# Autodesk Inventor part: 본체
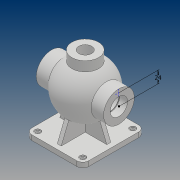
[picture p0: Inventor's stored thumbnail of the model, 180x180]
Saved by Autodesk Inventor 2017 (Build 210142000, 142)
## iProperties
Part Number: 본체
Material: 일반
Document SubType Name: Modeling
Designer: 13
Density: 1 g/cm^3
Appearance: 기본값
Author: 13
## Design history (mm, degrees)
sketch "스케치2"
  geometry: L1 (68, 0)-(-68, 0); L2 (68, 17.5)-(39.278, 17.5); L3 (-68, 17.5)-(-68, 31); L4 (-68, 31)-(-42.988, 31); L5 (42.988, 31)-(68, 31); L6 (68, 31)-(68, 17.5); L7 (-39.278, 17.5)-(-50.25, 17.5); L8 (-50.25, 17.5)-(-50.25, 18.5); L9 (-50.25, 18.5)-(-52, 18.5); L10 (-52, 18.5)-(-52, 17.5); L11 (-52, 17.5)-(-68, 17.5); A1 r 43 centre (0, 0) between (39.278, 17.5) and (-39.278, 17.5); A2 r 53 centre (0, 0) between (42.988, 31) and (-42.988, 31); 2 further points
  constraints: 22 end point, 6 horizontal, 5 point on line, 4 point on circle, 4 vertical, 3 coincident, 2 centre point, 1 midpoint
  dimensions: "d0" = 136 distance of L1.start L1.end; "d1" = 35 diameter of L2 L1; "d2" = 62 diameter of L5 L1; "d4" = 43 radius of A1; "d6" = 53 radius of A2; "d33" = 1.75 distance of L8.end L9.end; "d34" = 37 diameter of L9 L1; "d35" = 35 diameter of L7 L1; "d36" = 16 distance between parallel lines of L3 L10
revolve "회전1" sketch "스케치2" stored, may be unused: angle "d7" = 90 deg
node "작업 평면1"
sketch "스케치3"
  geometry: L1 (-57.5, 62.5)-(57.5, 62.5); L2 (57.5, 62.5)-(57.5, -62.5); L3 (57.5, -62.5)-(-57.5, -62.5); L4 (-57.5, -62.5)-(-57.5, 62.5); L5 (-57.5, 62.5)-(57.5, -62.5); L6 (57.5, 62.5)-(-57.5, -62.5); 1 further point
  constraints: 12 end point, 2 midpoint, 2 parallel, 1 horizontal, 1 perpendicular
  dimensions: "d9" = 115 distance of L2.end L3.end; "d10" = 125 distance of L1.end L2.end
extrude "돌출1" join sketch "스케치3" distance "d11" = 10; taper "d12" = 0 deg
sketch "스케치5"
  geometry: L1 (-4, -52.5)-(4, -52.5); L2 (4, -52.5)-(4, 52.5); L3 (4, 52.5)-(-4, 52.5); L4 (-4, 52.5)-(-4, -52.5); L5 (-4, -52.5)-(4, 52.5); L6 (4, -52.5)-(-4, 52.5); L7 (57.5, -62.5)-(-57.5, -62.5) reference; 1 further point
  constraints: 12 end point, 2 midpoint, 2 parallel, 1 horizontal, 1 perpendicular
  dimensions: "d15" = 8 distance of L2.end L3.end; "d16" = 10 distance between parallel lines of L7 L1
extrude "돌출2" join sketch "스케치5" stored distance "d17" = 10; taper "d18" = 0 deg
feature "면 기울기1" dims angle "d19" = 22 deg
feature "면 기울기2" dims angle "d20" = 22 deg
sketch "스케치6"
  geometry: L1 (-47.5, -4)-(47.5, -4); L2 (47.5, -4)-(47.5, 4); L3 (47.5, 4)-(-47.5, 4); L4 (-47.5, 4)-(-47.5, -4); L5 (-47.5, -4)-(47.5, 4); L6 (47.5, -4)-(-47.5, 4); L7 (-57.5, -62.5)-(-57.5, 62.5) reference; 1 further point
  constraints: 12 end point, 2 midpoint, 2 parallel, 1 horizontal, 1 perpendicular
  dimensions: "d21" = 8 distance of L1.end L2.end; "d22" = 10 distance between parallel lines of L7 L4
extrude "돌출3" join sketch "스케치6" stored distance "d23" = 10; taper "d24" = 0 deg
feature "면 기울기3" dims angle "d25" = 22 deg
node "작업 평면2"
sketch "스케치7"
  geometry: C1 r 27 at (0, 0); 1 further point
  constraints: 1 centre point, 1 coincident
  dimensions: "d27" = 54 diameter of C1
extrude "돌출4" join sketch "스케치7" stored distance "d28" = 10; taper "d29" = 0 deg
sketch "스케치8"
  geometry: C1 r 13 at (0, 0); 1 further point
  constraints: 1 centre point, 1 coincident
  dimensions: "d30" = 26 diameter of C1
extrude "돌출5" cut sketch "스케치8" distance "d31" = 30; taper "d32" = 0 deg
fillet "모깎기1" dims "d37" = 12
hole "구멍1" diameter "d40" = 8; stored, may be unused: countersink angle "d44" = 90 deg, drill point angle "d46" = 118 deg; dims "d38" = 10, "d39" = 10, "d41" = 6, "d42" = 12, "d43" = 3, "d45" = 8
hole "구멍2" diameter "d49" = 8; stored, may be unused: countersink angle "d53" = 90 deg, drill point angle "d55" = 118 deg; dims "d47" = 10, "d48" = 10, "d50" = 6, "d51" = 12, "d52" = 3, "d54" = 8
hole "구멍3" diameter "d58" = 8; stored, may be unused: countersink angle "d62" = 90 deg, drill point angle "d64" = 118 deg; dims "d56" = 10, "d57" = 10, "d59" = 6, "d60" = 12, "d61" = 3, "d63" = 8
hole "구멍4" diameter "d67" = 8; stored, may be unused: countersink angle "d71" = 90 deg, drill point angle "d73" = 118 deg; dims "d65" = 10, "d66" = 10, "d68" = 6, "d69" = 12, "d70" = 3, "d72" = 8
sketch "스케치9"
  geometry: 2 further points
  constraints: 1 horizontal alignment
  dimensions: "d74" = 24 distance of point (0, 0) point (-24, 0)
node "솔리드1"
other parameters: "d8" = -85
